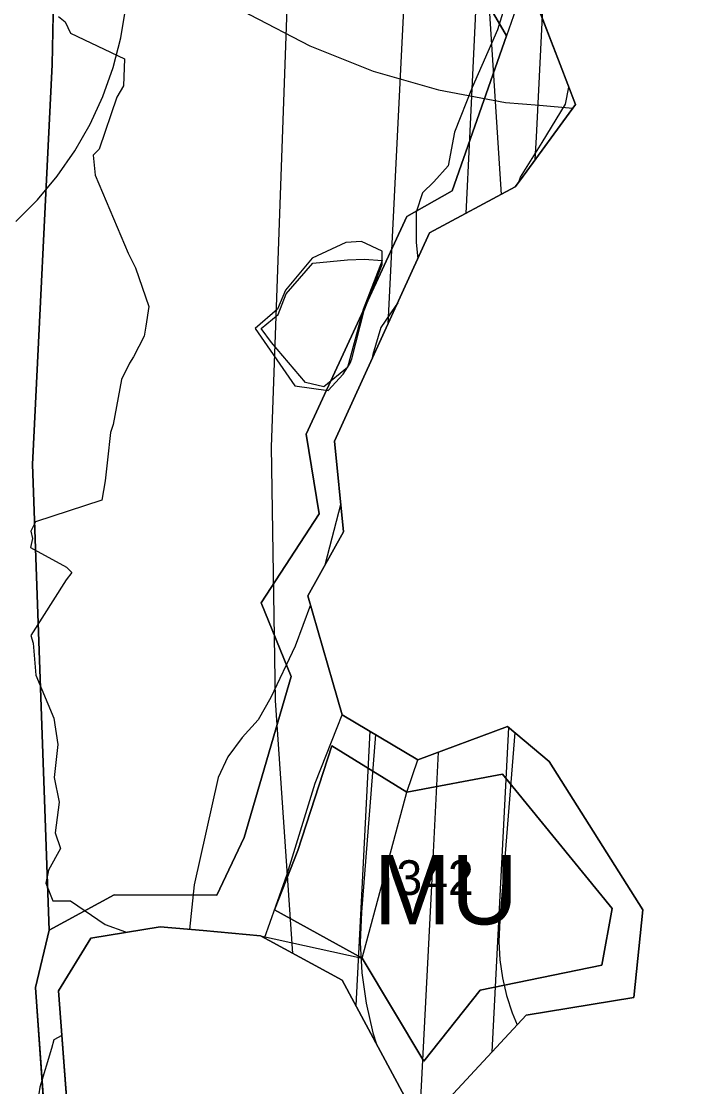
# Model space of a CAD drawing. Extents: x -690419 to -685080, y -987825 to -981190.
# Drawn here: x -686917.1 to -686820.2, y -987604.4 to -987450.7 of the extents above; entities that cross this region are included whole.
import ezdxf

# ---------------------------------------------------------------- set-up
doc = ezdxf.new("R2010")
doc.units = 0
for name, color, linetype in [('BP VTL plynovodu a RS (S)', 7, 'Continuous'), ('BPEJ (S) - hranice', 7, 'Continuous'), ('BPEJ I-II ochrana', 7, 'Continuous'), ('Elektro VN 35 nadzemní (S)', 7, 'Continuous'), ('Hranice řešeného území (S)', 7, 'Continuous'), ('Katastrální území (S) - hranice', 7, 'Continuous'), ('OP elektro VN (S)', 7, 'Continuous'), ('OP lesa 30 m (S)', 7, 'Continuous'), ('OP lesa 50 m (S)', 7, 'Continuous'), ('OP silnic (S)', 7, 'Continuous'), ('Plochy dopravy silniční DS (S)', 7, 'Continuous'), ('Plochy smíšené nezastavěného území všeobecné MU (S)', 7, 'Continuous'), ('Plochy vodní a vodnich toku WT (S)', 7, 'Continuous'), ('Regulacni bloky_ID', 7, 'Continuous'), ('Regulační bloky STABILIZOVANÉ (S)', 7, 'Continuous'), ('Regulační bloky STABILIZOVANÉ (S) TIS', 7, 'Continuous'), ('Regulační kódy STABILIZOVANÉ (S)', 7, 'Continuous'), ('USES LBK (S)', 7, 'Continuous'), ('USES_ŠRAFY (S)', 7, 'Continuous'), ('Záplavové území aktivní zóna (S)', 7, 'Continuous'), ('Záplavové území Q100 (S)', 7, 'Continuous')]:
    doc.layers.add(name, color=color, linetype=linetype)

msp = doc.modelspace()

# ---------------------------------------------------------------- linework, layer by layer
at = {"layer": 'BP VTL plynovodu a RS (S)'}
msp.add_lwpolyline([(-686919.04, -987415.77), (-686913.47, -987423.87), (-686907.14, -987431.38), (-686900.1, -987438.23), (-686892.42, -987444.36), (-686884.18, -987449.71), (-686875.45, -987454.22), (-686866.32, -987457.86), (-686856.88, -987460.59), (-686847.22, -987462.38), (-686842.33, -987462.79), (-686837.52, -987463.2)], dxfattribs=at)
at = {"layer": 'BPEJ (S) - hranice'}
for points in [[(-686843.38, -987446.39), (-686839.33, -987456.93), (-686837.13, -987462.67), (-686845.05, -987473.54), (-686845.8, -987474.57), (-686858.16, -987481.21), (-686871.87, -987511.25), (-686870.61, -987524.32), (-686875.73, -987533.58), (-686872.14, -987546.06), (-686870.8, -987550.72), (-686859.89, -987557.2), (-686846.92, -987552.4), (-686840.92, -987557.46), (-686827.37, -987578.87), (-686828.69, -987591.51), (-686844.22, -987594.07), (-686855.95, -987606.71)], [(-686861.77, -987605.76), (-686870.78, -987588.99), (-686881.34, -987583.3), (-686882.59, -987582.62), (-686890.86, -987581.86), (-686897.04, -987581.3), (-686907.04, -987582.95), (-686911.74, -987590.54), (-686907.88, -987641.59)]]:
    msp.add_lwpolyline(points, dxfattribs=at)
at = {"layer": 'BPEJ I-II ochrana'}
for p, q in [((-686912.26, -987437.97), (-686912.66, -987456.94)), ((-686847.08, -987452.77), (-686849.27, -987448.97)), ((-686854.91, -987475.14), (-686847.08, -987452.77)), ((-686912.66, -987456.94), (-686915.48, -987514.61)), ((-686861.47, -987478.83), (-686854.91, -987475.14)), ((-686875.98, -987510.22), (-686861.47, -987478.83)), ((-686874.13, -987521.74), (-686875.98, -987510.22)), ((-686915.48, -987514.61), (-686913.09, -987581.77)), ((-686882.46, -987534.59), (-686874.13, -987521.74)), ((-686878.13, -987545.19), (-686882.46, -987534.59)), ((-686884.94, -987568.44), (-686878.13, -987545.19)), ((-686872.26, -987555.2), (-686877.17, -987570.3)), ((-686861.45, -987561.87), (-686872.26, -987555.2)), ((-686847.63, -987559.3), (-686861.45, -987561.87)), ((-686831.8, -987578.68), (-686847.63, -987559.3)), ((-686888.89, -987576.75), (-686884.94, -987568.44)), ((-686877.17, -987570.3), (-686880.56, -987578.87)), ((-686913.09, -987581.77), (-686903.7, -987576.71)), ((-686903.7, -987576.71), (-686888.89, -987576.75)), ((-686833.32, -987586.83), (-686831.8, -987578.68)), ((-686880.56, -987578.87), (-686867.88, -987585.85)), ((-686867.88, -987585.85), (-686859.01, -987600.71)), ((-686850.89, -987590.43), (-686833.32, -987586.83)), ((-686859.01, -987600.71), (-686850.89, -987590.43))]:
    msp.add_line(p, q, dxfattribs=at)
at = {"layer": 'Elektro VN 35 nadzemní (S)'}
for points in [[(-686842.06, -987257.67), (-686848.08, -987376.25), (-686852.4, -987467.54), (-686852.96, -987478.41)], [(-686856.93, -987556.1), (-686857.96, -987576.32), (-686859.47, -987606.13)]]:
    msp.add_lwpolyline(points, dxfattribs=at)
at = {"layer": 'Hranice řešeného území (S)'}
for points in [[(-686843.38, -987446.39), (-686839.33, -987456.93), (-686837.13, -987462.67), (-686845.05, -987473.54), (-686845.8, -987474.57), (-686858.16, -987481.21), (-686871.87, -987511.25), (-686870.61, -987524.32), (-686875.73, -987533.58), (-686872.14, -987546.06), (-686870.8, -987550.72), (-686859.89, -987557.2), (-686846.92, -987552.4), (-686840.92, -987557.46), (-686827.37, -987578.87), (-686828.69, -987591.51), (-686844.22, -987594.07), (-686855.95, -987606.71)], [(-686861.77, -987605.76), (-686870.78, -987588.99), (-686881.34, -987583.3), (-686882.59, -987582.62), (-686890.86, -987581.86), (-686897.04, -987581.3), (-686907.04, -987582.95), (-686911.74, -987590.54), (-686907.88, -987641.59)]]:
    msp.add_lwpolyline(points, dxfattribs=at)
at = {"layer": 'Katastrální území (S) - hranice'}
for points in [[(-686855.95, -987606.71), (-686844.22, -987594.07), (-686828.69, -987591.51), (-686827.37, -987578.87), (-686840.92, -987557.46), (-686846.92, -987552.4), (-686859.89, -987557.2), (-686870.8, -987550.72), (-686872.14, -987546.06), (-686875.73, -987533.58), (-686870.61, -987524.32), (-686871.87, -987511.25), (-686858.16, -987481.21), (-686845.8, -987474.57), (-686845.05, -987473.54), (-686837.13, -987462.67), (-686839.33, -987456.93), (-686843.38, -987446.39)], [(-686907.88, -987641.59), (-686911.74, -987590.54), (-686907.04, -987582.95), (-686897.04, -987581.3), (-686890.86, -987581.86), (-686882.59, -987582.62), (-686881.34, -987583.3), (-686870.78, -987588.99), (-686861.77, -987605.76)]]:
    msp.add_lwpolyline(points, dxfattribs=at)
at = {"layer": 'OP elektro VN (S)'}
for points in [[(-686842.91, -987470.61), (-686842.75, -987467.42), (-686832.37, -987257.21), (-686805.58, -987153.72), (-686779.27, -987051.03), (-686771.29, -987017.8), (-686728.86, -986970.69), (-686666.98, -986901.96), (-686664.58, -986904.71), (-686492.19, -987102.65), (-686397.96, -987316.5), (-686339.43, -987449.15)], [(-687203.89, -987498.03), (-687010.41, -987283.28), (-686933.14, -987197.49), (-686852.61, -987261.32), (-686864.18, -987494.39)], [(-686849.12, -987599.35), (-686847.98, -987576.83), (-686846.74, -987552.56)], [(-686866.79, -987553.1), (-686867.95, -987575.81), (-686868.8, -987592.67)]]:
    msp.add_lwpolyline(points, dxfattribs=at)
at = {"layer": 'OP lesa 30 m (S)'}
msp.add_lwpolyline([(-686845.87, -987553.28), (-686848.05, -987580.36), (-686848.16, -987583.43), (-686848.02, -987586.06), (-686847.66, -987588.67), (-686847.06, -987591.24), (-686846.24, -987593.74), (-686845.51, -987595.46)], dxfattribs=at)
at = {"layer": 'OP lesa 50 m (S)'}
for points in [[(-686849.6, -987448.09), (-686847.85, -987475.67)], [(-686917.88, -987479.56), (-686914.74, -987476.43), (-686911.9, -987473.03), (-686909.37, -987469.39), (-686907.17, -987465.54), (-686905.32, -987461.52), (-686903.84, -987457.34), (-686902.73, -987453.05), (-686902, -987448.68)], [(-686865.96, -987553.59), (-686868.02, -987579.19), (-686868.18, -987583.59), (-686867.95, -987587.97), (-686867.34, -987592.33), (-686866.35, -987596.61), (-686865.82, -987598.22)]]:
    msp.add_lwpolyline(points, dxfattribs=at)
at = {"layer": 'OP silnic (S)'}
msp.add_lwpolyline([(-686877.9, -987585.15), (-686880.4, -987548.64), (-686880.98, -987512.09), (-686878.64, -987446.11), (-686871.78, -987385.76), (-686863.13, -987331.7), (-686839.14, -987225.07), (-686789.33, -987012.8)], dxfattribs=at)
at = {"layer": 'Plochy dopravy silniční DS (S)'}
for p, q in [((-686912.26, -987437.97), (-686912.66, -987456.94)), ((-686912.66, -987456.94), (-686915.48, -987514.61)), ((-686915.48, -987514.61), (-686913.09, -987581.77)), ((-686913.09, -987581.77), (-686915.05, -987590.07)), ((-686915.05, -987590.07), (-686910.83, -987649.41))]:
    msp.add_line(p, q, dxfattribs=at)
at = {"layer": 'Plochy smíšené nezastavěného území všeobecné MU (S)'}
msp.add_lwpolyline([(-686849.27, -987448.97), (-686847.08, -987452.77), (-686854.91, -987475.14), (-686861.47, -987478.83), (-686875.98, -987510.22), (-686874.13, -987521.74), (-686882.46, -987534.59), (-686878.13, -987545.19), (-686884.94, -987568.44), (-686888.89, -987576.75), (-686903.7, -987576.71), (-686913.09, -987581.77), (-686915.48, -987514.61), (-686912.66, -987456.94), (-686912.26, -987437.97)], dxfattribs=at)
msp.add_lwpolyline([(-686859.01, -987600.71), (-686867.88, -987585.85), (-686880.56, -987578.87), (-686877.17, -987570.3), (-686872.26, -987555.2), (-686861.45, -987561.87), (-686847.63, -987559.3), (-686831.8, -987578.68), (-686833.32, -987586.83), (-686850.89, -987590.43)], close=True, dxfattribs=at)
at = {"layer": 'Plochy vodní a vodnich toku WT (S)'}
for p, q in [((-686843.38, -987446.39), (-686839.33, -987456.93)), ((-686847.08, -987452.77), (-686849.27, -987448.97)), ((-686854.91, -987475.14), (-686847.08, -987452.77)), ((-686839.33, -987456.93), (-686837.13, -987462.67)), ((-686837.13, -987462.67), (-686845.05, -987473.54)), ((-686845.05, -987473.54), (-686845.8, -987474.57)), ((-686861.47, -987478.83), (-686854.91, -987475.14)), ((-686845.8, -987474.57), (-686858.16, -987481.21)), ((-686875.98, -987510.22), (-686861.47, -987478.83)), ((-686858.16, -987481.21), (-686871.87, -987511.25)), ((-686874.13, -987521.74), (-686875.98, -987510.22)), ((-686871.87, -987511.25), (-686870.61, -987524.32)), ((-686882.46, -987534.59), (-686874.13, -987521.74)), ((-686870.61, -987524.32), (-686875.73, -987533.58)), ((-686875.73, -987533.58), (-686872.14, -987546.06)), ((-686878.13, -987545.19), (-686882.46, -987534.59)), ((-686884.94, -987568.44), (-686878.13, -987545.19)), ((-686872.14, -987546.06), (-686870.8, -987550.72)), ((-686870.8, -987550.72), (-686859.89, -987557.2)), ((-686859.89, -987557.2), (-686846.92, -987552.4)), ((-686846.92, -987552.4), (-686840.92, -987557.46)), ((-686872.26, -987555.2), (-686877.17, -987570.3)), ((-686861.45, -987561.87), (-686872.26, -987555.2)), ((-686840.92, -987557.46), (-686827.37, -987578.87)), ((-686847.63, -987559.3), (-686861.45, -987561.87)), ((-686831.8, -987578.68), (-686847.63, -987559.3)), ((-686888.89, -987576.75), (-686884.94, -987568.44)), ((-686877.17, -987570.3), (-686880.56, -987578.87)), ((-686913.09, -987581.77), (-686903.7, -987576.71)), ((-686903.7, -987576.71), (-686888.89, -987576.75)), ((-686833.32, -987586.83), (-686831.8, -987578.68)), ((-686880.56, -987578.87), (-686867.88, -987585.85)), ((-686827.37, -987578.87), (-686828.69, -987591.51)), ((-686915.05, -987590.07), (-686913.09, -987581.77)), ((-686897.04, -987581.3), (-686907.04, -987582.95)), ((-686890.86, -987581.86), (-686897.04, -987581.3)), ((-686882.59, -987582.62), (-686890.86, -987581.86)), ((-686907.04, -987582.95), (-686911.74, -987590.54)), ((-686881.34, -987583.3), (-686882.59, -987582.62)), ((-686870.78, -987588.99), (-686881.34, -987583.3)), ((-686867.88, -987585.85), (-686859.01, -987600.71)), ((-686850.89, -987590.43), (-686833.32, -987586.83)), ((-686861.77, -987605.76), (-686870.78, -987588.99)), ((-686910.83, -987649.41), (-686915.05, -987590.07)), ((-686911.74, -987590.54), (-686907.88, -987641.59)), ((-686859.01, -987600.71), (-686850.89, -987590.43)), ((-686828.69, -987591.51), (-686844.22, -987594.07)), ((-686844.22, -987594.07), (-686855.95, -987606.71))]:
    msp.add_line(p, q, dxfattribs=at)
at = {"layer": 'Regulační bloky STABILIZOVANÉ (S)'}
for p, q in [((-686912.26, -987437.97), (-686912.66, -987456.94)), ((-686843.38, -987446.39), (-686839.33, -987456.93)), ((-686847.08, -987452.77), (-686849.27, -987448.97)), ((-686854.91, -987475.14), (-686847.08, -987452.77)), ((-686912.66, -987456.94), (-686915.48, -987514.61)), ((-686839.33, -987456.93), (-686837.13, -987462.67)), ((-686837.13, -987462.67), (-686845.05, -987473.54)), ((-686845.05, -987473.54), (-686845.8, -987474.57)), ((-686861.47, -987478.83), (-686854.91, -987475.14)), ((-686845.8, -987474.57), (-686858.16, -987481.21)), ((-686875.98, -987510.22), (-686861.47, -987478.83)), ((-686858.16, -987481.21), (-686871.87, -987511.25)), ((-686874.13, -987521.74), (-686875.98, -987510.22)), ((-686871.87, -987511.25), (-686870.61, -987524.32)), ((-686915.48, -987514.61), (-686913.09, -987581.77)), ((-686882.46, -987534.59), (-686874.13, -987521.74)), ((-686870.61, -987524.32), (-686875.73, -987533.58)), ((-686875.73, -987533.58), (-686872.14, -987546.06)), ((-686878.13, -987545.19), (-686882.46, -987534.59)), ((-686884.94, -987568.44), (-686878.13, -987545.19)), ((-686872.14, -987546.06), (-686870.8, -987550.72)), ((-686870.8, -987550.72), (-686859.89, -987557.2)), ((-686859.89, -987557.2), (-686846.92, -987552.4)), ((-686846.92, -987552.4), (-686840.92, -987557.46)), ((-686872.26, -987555.2), (-686877.17, -987570.3)), ((-686861.45, -987561.87), (-686872.26, -987555.2)), ((-686840.92, -987557.46), (-686827.37, -987578.87)), ((-686847.63, -987559.3), (-686861.45, -987561.87)), ((-686831.8, -987578.68), (-686847.63, -987559.3)), ((-686888.89, -987576.75), (-686884.94, -987568.44)), ((-686877.17, -987570.3), (-686880.56, -987578.87)), ((-686913.09, -987581.77), (-686903.7, -987576.71)), ((-686903.7, -987576.71), (-686888.89, -987576.75)), ((-686833.32, -987586.83), (-686831.8, -987578.68)), ((-686880.56, -987578.87), (-686867.88, -987585.85)), ((-686827.37, -987578.87), (-686828.69, -987591.51)), ((-686915.05, -987590.07), (-686913.09, -987581.77)), ((-686913.09, -987581.77), (-686915.05, -987590.07)), ((-686897.04, -987581.3), (-686907.04, -987582.95)), ((-686890.86, -987581.86), (-686897.04, -987581.3)), ((-686882.59, -987582.62), (-686890.86, -987581.86)), ((-686907.04, -987582.95), (-686911.74, -987590.54)), ((-686881.34, -987583.3), (-686882.59, -987582.62)), ((-686870.78, -987588.99), (-686881.34, -987583.3)), ((-686867.88, -987585.85), (-686859.01, -987600.71)), ((-686850.89, -987590.43), (-686833.32, -987586.83)), ((-686861.77, -987605.76), (-686870.78, -987588.99)), ((-686910.83, -987649.41), (-686915.05, -987590.07)), ((-686915.05, -987590.07), (-686910.83, -987649.41)), ((-686911.74, -987590.54), (-686907.88, -987641.59)), ((-686859.01, -987600.71), (-686850.89, -987590.43)), ((-686828.69, -987591.51), (-686844.22, -987594.07)), ((-686844.22, -987594.07), (-686855.95, -987606.71))]:
    msp.add_line(p, q, dxfattribs=at)
msp.add_lwpolyline([(-686849.27, -987448.97), (-686847.08, -987452.77), (-686854.91, -987475.14), (-686861.47, -987478.83), (-686875.98, -987510.22), (-686874.13, -987521.74), (-686882.46, -987534.59), (-686878.13, -987545.19), (-686884.94, -987568.44), (-686888.89, -987576.75), (-686903.7, -987576.71), (-686913.09, -987581.77), (-686915.48, -987514.61), (-686912.66, -987456.94), (-686912.26, -987437.97)], dxfattribs=at)
msp.add_lwpolyline([(-686859.01, -987600.71), (-686867.88, -987585.85), (-686880.56, -987578.87), (-686877.17, -987570.3), (-686872.26, -987555.2), (-686861.45, -987561.87), (-686847.63, -987559.3), (-686831.8, -987578.68), (-686833.32, -987586.83), (-686850.89, -987590.43)], close=True, dxfattribs=at)
at = {"layer": 'Regulační bloky STABILIZOVANÉ (S) TIS'}
for p, q in [((-686839.33, -987456.93), (-686843.38, -987446.39)), ((-686847.08, -987452.77), (-686854.91, -987475.14)), ((-686845.8, -987474.57), (-686845.05, -987473.54)), ((-686854.91, -987475.14), (-686861.47, -987478.83)), ((-686861.47, -987478.83), (-686875.98, -987510.22)), ((-686875.98, -987510.22), (-686874.13, -987521.74)), ((-686874.13, -987521.74), (-686882.46, -987534.59)), ((-686882.46, -987534.59), (-686878.13, -987545.19)), ((-686878.13, -987545.19), (-686884.94, -987568.44)), ((-686840.92, -987557.46), (-686846.92, -987552.4)), ((-686872.26, -987555.2), (-686861.45, -987561.87)), ((-686884.94, -987568.44), (-686888.89, -987576.75)), ((-686913.09, -987581.77), (-686915.05, -987590.07)), ((-686911.74, -987590.54), (-686907.04, -987582.95)), ((-686915.05, -987590.07), (-686910.83, -987649.41)), ((-686907.88, -987641.59), (-686911.74, -987590.54)), ((-686850.89, -987590.43), (-686859.01, -987600.71))]:
    msp.add_line(p, q, dxfattribs=at)
for points in [[(-686841.34, -987436.37), (-686846.79, -987436.76), (-686849.27, -987448.97), (-686847.08, -987452.77)], [(-686845.05, -987473.54), (-686837.13, -987462.67), (-686839.33, -987456.93)], [(-686872.14, -987546.06), (-686875.73, -987533.58), (-686870.61, -987524.32), (-686871.87, -987511.25), (-686858.16, -987481.21), (-686845.8, -987474.57)], [(-686846.92, -987552.4), (-686859.89, -987557.2), (-686870.8, -987550.72), (-686872.14, -987546.06)], [(-686880.56, -987578.87), (-686877.17, -987570.3), (-686872.26, -987555.2)], [(-686855.95, -987606.71), (-686844.22, -987594.07), (-686828.69, -987591.51), (-686827.37, -987578.87), (-686840.92, -987557.46)], [(-686861.45, -987561.87), (-686847.63, -987559.3), (-686831.8, -987578.68)], [(-686888.89, -987576.75), (-686903.7, -987576.71), (-686913.09, -987581.77)], [(-686831.8, -987578.68), (-686833.32, -987586.83), (-686850.89, -987590.43)], [(-686859.01, -987600.71), (-686867.88, -987585.85), (-686880.56, -987578.87)], [(-686907.04, -987582.95), (-686897.04, -987581.3), (-686890.86, -987581.86)], [(-686890.86, -987581.86), (-686882.59, -987582.62), (-686881.34, -987583.3)], [(-686881.34, -987583.3), (-686870.78, -987588.99), (-686861.77, -987605.76)]]:
    msp.add_lwpolyline(points, dxfattribs=at)
at = {"layer": 'USES LBK (S)'}
for points in [[(-686841.34, -987436.37), (-686847.08, -987452.77), (-686854.91, -987475.14), (-686861.47, -987478.83), (-686875.98, -987510.22), (-686874.13, -987521.74), (-686882.46, -987534.59), (-686878.13, -987545.19), (-686884.94, -987568.44), (-686888.89, -987576.75), (-686903.7, -987576.71), (-686913.09, -987581.77), (-686915.05, -987590.07), (-686910.83, -987649.41)], [(-686907.88, -987641.59), (-686911.74, -987590.54), (-686907.04, -987582.95), (-686897.04, -987581.3), (-686890.86, -987581.86), (-686882.59, -987582.62), (-686867.88, -987585.85), (-686861.45, -987561.87), (-686859.89, -987557.2), (-686870.8, -987550.72), (-686872.14, -987546.06), (-686875.73, -987533.58), (-686870.61, -987524.32), (-686871.87, -987511.25), (-686858.16, -987481.21), (-686845.8, -987474.57), (-686845.05, -987473.54), (-686837.13, -987462.67), (-686839.33, -987456.93), (-686843.38, -987446.39)]]:
    msp.add_lwpolyline(points, dxfattribs=at)
at = {"layer": 'USES_ŠRAFY (S)'}
for points in [[(-686841.34, -987436.37), (-686847.08, -987452.77), (-686854.91, -987475.14), (-686861.47, -987478.83), (-686875.98, -987510.22), (-686874.13, -987521.74), (-686882.46, -987534.59), (-686878.13, -987545.19), (-686884.94, -987568.44), (-686888.89, -987576.75), (-686903.7, -987576.71), (-686913.09, -987581.77), (-686915.05, -987590.07), (-686910.83, -987649.41)], [(-686907.88, -987641.59), (-686911.74, -987590.54), (-686907.04, -987582.95), (-686897.04, -987581.3), (-686890.86, -987581.86), (-686882.59, -987582.62), (-686867.88, -987585.85), (-686861.45, -987561.87), (-686859.89, -987557.2), (-686870.8, -987550.72), (-686872.14, -987546.06), (-686875.73, -987533.58), (-686870.61, -987524.32), (-686871.87, -987511.25), (-686858.16, -987481.21), (-686845.8, -987474.57), (-686845.05, -987473.54), (-686837.13, -987462.67), (-686839.33, -987456.93), (-686843.38, -987446.39)]]:
    msp.add_lwpolyline(points, dxfattribs=at)
at = {"layer": 'Záplavové území aktivní zóna (S)'}
for points in [[(-686843.52, -987436.03), (-686848.35, -987451.91), (-686852.04, -987460.22), (-686854.58, -987466.68), (-686855.51, -987471.53), (-686857.58, -987473.84), (-686859.2, -987475.45), (-686860.12, -987478.22), (-686860.12, -987482.61), (-686859.86, -987484.94)], [(-686845.29, -987473.87), (-686845.03, -987473.17), (-686841.92, -987468.16), (-686838.56, -987462.63), (-686838.08, -987460.18)], [(-686862.77, -987491.32), (-686863.12, -987491.84), (-686865.2, -987494.84), (-686866.35, -987498.77), (-686866.49, -987499.45)], [(-686871, -987520.26), (-686873.28, -987529.15)], [(-686875.36, -987534.88), (-686877.59, -987540.84), (-686881.06, -987548.23), (-686882.9, -987551.46), (-686885.21, -987554), (-686887.29, -987556.77), (-686888.67, -987559.77), (-686892.14, -987575.23), (-686892.8, -987581.68)], [(-686882, -987582.94), (-686878.71, -987573.72), (-686874.7, -987560.57), (-686871.5, -987552.56), (-686870.8, -987550.72)]]:
    msp.add_lwpolyline(points, dxfattribs=at)
msp.add_lwpolyline([(-686870.62, -987501.57), (-686869.64, -987500), (-686869.38, -987499.38), (-686867.61, -987492.39), (-686865, -987485.79), (-686865, -987483.86), (-686868.01, -987482.44), (-686870.26, -987482.6), (-686875.13, -987484.84), (-686878.96, -987489.49), (-686880.14, -987492.19), (-686883.36, -987495), (-686877.64, -987503.27), (-686872.82, -987503.94)], close=True, dxfattribs=at)
at = {"layer": 'Záplavové území Q100 (S)'}
for points in [[(-686911.75, -987450), (-686910.76, -987450.76), (-686910, -987452.4), (-686902.2, -987456.1), (-686902.35, -987460), (-686903.29, -987461.64), (-686905.86, -987469.14), (-686906.7, -987470), (-686906.45, -987472.9), (-686901.69, -987484.15), (-686900.61, -987486.23), (-686898.7, -987491.85), (-686899.13, -987494.68), (-686899.35, -987496.1), (-686900.92, -987499.08), (-686901.49, -987500), (-686902.65, -987502.35), (-686903.84, -987508.84), (-686904.24, -987510), (-686904.66, -987513.97), (-686905, -987516.97), (-686905.45, -987519.78), (-686915.04, -987522.87), (-686915.74, -987524.26), (-686915.47, -987525.27), (-686915.79, -987526.57), (-686910.56, -987529.44), (-686909.79, -987530.21), (-686910.63, -987531.26), (-686915.71, -987539.3), (-686915.39, -987540.39), (-686914.99, -987545.01), (-686912.39, -987551.2), (-686911.8, -987555.03), (-686912.37, -987559.75), (-686911.64, -987563.32), (-686912.23, -987567.77), (-686911.43, -987570), (-686913.16, -987573.16), (-686913.56, -987575), (-686912.56, -987577.56), (-686910, -987577.58), (-686905, -987580.98), (-686902.05, -987582.05), (-686901.96, -987582.11)], [(-686911.25, -987596.97), (-686912.38, -987597.62), (-686912.75, -987598.87), (-686914.42, -987604.42), (-686914.58, -987605.42), (-686912.83, -987612.83), (-686912.65, -987615), (-686912.07, -987617.07), (-686912.82, -987620), (-686912.28, -987622.58), (-686911.93, -987625), (-686911.72, -987626.72), (-686911.37, -987629.87), (-686911.23, -987630.98), (-686911.07, -987632.14), (-686911.35, -987634.21), (-686912.13, -987640), (-686911.65, -987641.65), (-686911.73, -987645), (-686912.24, -987647.76), (-686912.81, -987649.75), (-686915.63, -987654.22), (-686914.4, -987667.38)]]:
    msp.add_lwpolyline(points, dxfattribs=at)
msp.add_lwpolyline([(-686876.1, -987502.79), (-686881, -987497.01), (-686882.46, -987495), (-686880, -987492.98), (-686878.88, -987490), (-686875, -987485.58), (-686870, -987485.1), (-686867.54, -987485), (-686865, -987485.17), (-686867.76, -987492.24), (-686870, -987500.61), (-686873.42, -987503.42)], close=True, dxfattribs=at)

# ---------------------------------------------------------------- texts
at = {"layer": 'Regulacni bloky_ID'}
msp.add_text('342', height=5, dxfattribs=at).set_placement((-686862.96, -987576.71))
at = {"layer": 'Regulační kódy STABILIZOVANÉ (S)'}
msp.add_text('MU', height=10, dxfattribs=at).set_placement((-686866.21, -987580.96))

doc.saveas('drawing.dxf')
